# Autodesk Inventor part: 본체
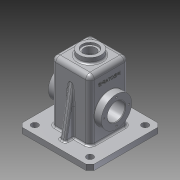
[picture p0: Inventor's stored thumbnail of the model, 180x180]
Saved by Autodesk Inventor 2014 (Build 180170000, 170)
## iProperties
Created: 2016-02
Part Number: 본체
Material: 알루미늄 6061
Document SubType Name: Modeling
Designer: aapexcom
Density: 2.71 g/cm^3
Appearance: 알루미늄 - 평지
Mass: 981.845 g
Surface Area: 1046.35 cm^2
Volume: 362.305 cm^3
Author: aapexcom
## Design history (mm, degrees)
sketch "스케치1"
  geometry: L1 (-57.935, 65)-(57.935, 65); L2 (65, 57.935)-(65, -57.935); L3 (57.935, -65)-(-57.935, -65); L4 (-65, -57.935)-(-65, 57.935); L5 (-65, 65)-(65, -65); L6 (65, 65)-(-65, -65); L7 (-82.011, 0)-(89.869, 0); L8 (-57.935, 65)-(-65.006, 57.929); L9 (-57.935, -65)-(-65.006, -57.929); L10 (0, 65)-(0, -95.925); L11 (57.935, 65)-(65.006, 57.929); L12 (57.935, -65)-(65.006, -57.929); 1 further point
  constraints: 24 end point, 6 symmetric about line, 4 parallel, 4 perpendicular, 4 point on line, 3 midpoint, 1 horizontal
  dimensions: "d0" = 130 distance of L5.start L6.start; "d1" = 130 distance of L6.end L5.start; "d51" = 10 distance of L1.start L8.end; "d52" = 86.92792 distance between parallel lines of L8 L6; "d53" = 65 distance between parallel lines of L7 L1; "d54" = 24.86887 distance from line of L7.end L2; "d55" = 147.01132 distance from line of L7.start L2; "d56" = 65 distance between parallel lines of L10 L2; "d57" = 130 distance between parallel lines of L4 L2; "d58" = 154.75749 distance from line of L10.end L11; "d59" = 86.92792 distance between parallel lines of L11 L5; "d60" = 173.85585 distance between parallel lines of L11 L9; "d61" = 0 distance from line of L6.start L2; "d62" = 0 distance from line of L5.end L2
extrude "돌출1" new body sketch "스케치1" distance "d2" = 10; taper "d3" = 0 deg
sketch "스케치2"
  geometry: L1 (-35, 35)-(35, 35); L2 (35, 35)-(35, -35); L3 (35, -35)-(-35, -35); L4 (-35, -35)-(-35, 35); L5 (-35, 35)-(35, -35); L6 (35, 35)-(-35, -35); 1 further point
  constraints: 12 end point, 2 midpoint, 2 parallel, 1 horizontal, 1 perpendicular
  dimensions: "d4" = 70 distance of L1.start L1.end; "d5" = 70 distance of L3.end L1.start
extrude "돌출2" join sketch "스케치2" distance "d6" = 110; taper "d7" = 0 deg
fillet "모깎기1" dims "d8" = 8
sketch "스케치3"
  geometry: C1 r 20 at (0, 0); 1 further point
  constraints: 1 centre point, 1 coincident
  dimensions: "d9" = 40 diameter of C1
extrude "돌출3" join sketch "스케치3" distance "d10" = 10; taper "d11" = 0 deg
sketch "스케치4"
  geometry: C1 r 20 at (0, 0) reference; C2 r 14 at (0, 0)
  constraints: 1 centre point, 1 coincident
  dimensions: "d12" = 28 diameter of C2
extrude "돌출4" cut sketch "스케치4" distance "d13" = 4; taper "d14" = 0 deg
sketch "스케치5"
  geometry: L1 (-30, 30)-(30, 30); L2 (30, 30)-(30, -30); L3 (30, -30)-(-30, -30); L4 (-30, -30)-(-30, 30); L5 (-30, 30)-(30, -30); L6 (30, 30)-(-30, -30); 1 further point
  constraints: 12 end point, 2 midpoint, 2 parallel, 1 horizontal, 1 perpendicular
  dimensions: "d15" = 60 distance of L1.start L1.end; "d16" = 60 distance of L3.end L1.start
extrude "돌출5" cut sketch "스케치5" distance "d17" = 115; taper "d18" = 0 deg
sketch "스케치6"
  geometry: C1 r 14 at (0, 0) reference; C2 r 10.5 at (0, 0)
  constraints: 1 centre point, 1 coincident
  dimensions: "d19" = 21 diameter of C2
extrude "돌출6" cut sketch "스케치6" stored distance "d20" = 115; taper "d21" = 0 deg
node "작업 평면1"
sketch "스케치7"
  geometry: L1 (0, 60)-(0, 0) reference; C1 r 27.5 at (-55, 30); 2 further points
  constraints: 1 centre point, 1 horizontal alignment, 1 midpoint
  dimensions: "d23" = 55 distance from line of L1 C1.centre; "d24" = 55 diameter of C1
extrude "돌출7" join sketch "스케치7" stored distance "d25" = 115; taper "d26" = 45 deg
sketch "스케치10"
  geometry: L1 (-10, 57)-(-10, -3) reference; C1 r 27.5 at (45, 27); 1 further point
  constraints: 1 centre point, 1 horizontal alignment
  dimensions: "d32" = 55 diameter of C1; "d33" = 55 distance from line of C1.centre L1
extrude "돌출9" join sketch "스케치10" distance "d34" = 13; taper "d35" = 0 deg
sketch "스케치11"
  geometry: C1 r 27.5 at (0, 0) reference; C2 r 16 at (0, 0); 1 further point
  constraints: 1 centre point, 1 coincident
  dimensions: "d36" = 32 diameter of C2
extrude "돌출10" cut sketch "스케치11" stored distance "d37" = 13; taper "d38" = 0 deg
sketch "스케치12" dims "d39" = 45
  geometry: L1 (0, 0)-(0, 22.5); C1 r 27.5 at (0, 0) reference; 1 further point
  constraints: 2 end point, 1 coincident, 1 vertical, 1 vertical alignment, 2 other
hole "구멍1" sketch "스케치12" at (0, 22.5) diameter "d40" = 3.242; stored, may be unused: countersink angle "d44" = 90 deg, drill point angle "d46" = 118 deg; dims "d41" = 8, "d42" = 4, "d43" = 2, "d45" = 10
sketch "스케치13"
  geometry: L1 (65, 57.935)-(57.935, 65) reference; L2 (57.935, 65)-(-57.935, 65) reference; L3 (27, -35)-(-27, -35) reference; L4 (-27, 35)-(27, 35) reference; L5 (-82.924, 0)-(100.555, 0); C1 r 6 at (-50, 50); C2 r 6 at (50, 50); C3 r 6 at (-50, -50); C4 r 6 at (50, -50); 1 further point
  constraints: 4 centre point, 2 end point, 2 symmetric about line, 1 parallel, 2 other
  dimensions: "d63" = 50 horizontal distance of C1.centre point (0, 0); "d64" = 15 distance from line of C1.centre L2; "d65" = 12 diameter of C1; "d66" = 50 horizontal distance of C2.centre point (0, 0); "d67" = 15 distance from line of C2.centre L2; "d68" = 12 diameter of C2; "d69" = 35 distance between parallel lines of L3 L5; "d70" = 15.82483 distance from line of L5.end L1; "d71" = 145.56421 distance from line of L5.start L1
extrude "돌출11" cut sketch "스케치13" distance "d72" = 10; taper "d73" = 0 deg
sketch "스케치14"
  geometry: L1 (57.935, 10)-(-57.935, 10) reference; L2 (-35, 10)-(-35, 112) reference; L3 (35, 112)-(35, 10) reference; L4 (35, 95.069)-(50, 10); L5 (65, 0)-(65, 10) reference; L6 (0, -22.061)-(0, 146.662); L7 (-35, 95.069)-(-50, 10); L8 (-35, 95.069)-(-35, 10); L9 (-50, 10)-(-35, 10); 3 further points
  constraints: 10 end point, 2 point on line, 2 symmetric about line, 1 collinear, 1 parallel
  dimensions: "d74" = 10 deg angle of L5 L4; "d75" = 15 distance from line of L4.end L5; "d76" = 35 distance between parallel lines of L2 L6; "d77" = 136.66209 distance from line of L6.end L1; "d78" = 32.06099 distance from line of L6.start L1
extrude "돌출12" join sketch "스케치14" stored distance "d79" = 10; taper "d80" = 0 deg
node "작업 평면2"
sketch "스케치15"
  geometry: L1 (20, 130)-(-20, 130) reference; L2 (35, 10)-(35, 112) reference; 3 further points
  constraints: 1 other
  dimensions: "d82" = 30 distance from line of point (0, 100) L1; "d83" = 35 distance from line of L2 point (0, 100)
feature "엠보싱1" sketch "스케치15" dims "d0" = 130, "d1" = 130, "d51" = 10, "d52" = 86.92792, "d53" = 65, "d54" = 24.86887, "d55" = 147.01132, "d56" = 65, "d57" = 130, "d58" = 154.75749, "d59" = 86.92792, "d60" = 173.85585, "d61" = 0, "d62" = 0, "d84" = 0.5, "d85" = 0
fillet "모깎기2" dims "d86" = 3
fillet "모깎기3" dims "d87" = 3
chamfer "모따기1" distance "d88" = 1; stored, may be unused: second distance "d89" = 2, angle "d90" = 45 deg
fillet "모깎기4" dims "d91" = 0.5
node "솔리드1"
pattern_circular "원형 패턴1" dims angle "d48" = 360 deg
mirror "대칭1"
mirror "대칭2"
other parameters: "d22" = 7, "d81" = 67.5
